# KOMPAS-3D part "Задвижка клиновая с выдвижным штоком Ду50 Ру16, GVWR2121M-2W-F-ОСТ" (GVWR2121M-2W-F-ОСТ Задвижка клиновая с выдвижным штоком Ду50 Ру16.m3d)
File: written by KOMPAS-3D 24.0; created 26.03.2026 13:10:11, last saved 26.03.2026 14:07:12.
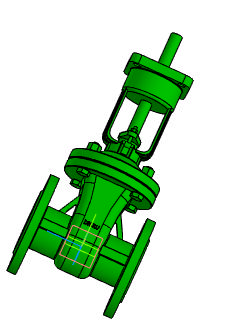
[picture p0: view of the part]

Document properties: Автор: R2D2; Полное имя файла: E:\Работа\Зайцев\GVWR2121M-2W-F-ОСТ Задвижка клиновая с видвижным штоком Ду50-300 Ру16\DN50\GVWR2121M-2W-F-ОСТ Задвижка клиновая с выдвижным штоком Ду50 Ру16.m3d

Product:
- Part/product: Задвижка клиновая с выдвижным штоком Ду50 Ру16  | designation GVWR2121M-2W-F-ОСТ
    Масса: 12
    Раздел спецификации: Прочие изделия
    Примечание: D040-08598

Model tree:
1. Операция без истории:1

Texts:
  GVWR2121M-2W-F-ОСТ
